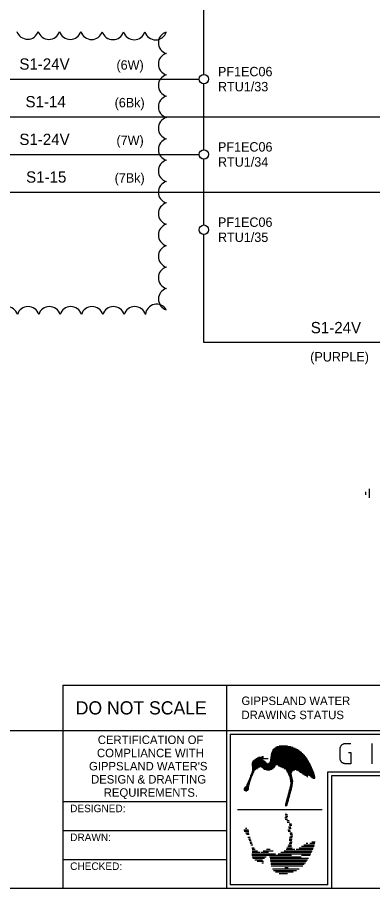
# Model space of a CAD drawing. Extents: x 0 to 841, y 0 to 594.
# Drawn here: x 580.4 to 674.9, y 15 to 246.4 of the extents above; entities that cross this region are included whole.
import ezdxf

# ---------------------------------------------------------------- set-up
doc = ezdxf.new("R2010")
doc.units = 0
for name, color, linetype in [('A1BORDER', 7, 'Continuous'), ('Level 1', 7, 'Continuous'), ('Level 10', 7, 'Continuous'), ('Level 2', 7, 'Continuous')]:
    doc.layers.add(name, color=color, linetype=linetype)

msp = doc.modelspace()

# ---------------------------------------------------------------- linework, layer by layer
at = {"layer": 'A1BORDER'}
for p, q in [((592.5, 69), (592.5, 15)), ((592.5, 69), (829, 69)), ((636, 69), (636, 15)), ((28, 57), (829, 57)), ((637, 56), (788, 56)), ((637, 56), (637, 16)), ((647.91, 50.92), (656.3, 50.92)), ((647.96, 51.12), (656.08, 51.12)), ((648.03, 51.32), (655.85, 51.32)), ((648.12, 51.52), (655.59, 51.52)), ((648.23, 51.72), (655.31, 51.72)), ((648.37, 51.92), (655, 51.92)), ((648.53, 52.12), (654.64, 52.12)), ((648.74, 52.32), (654.24, 52.32)), ((649.02, 52.52), (653.76, 52.52)), ((649.39, 52.72), (653.15, 52.72)), ((650.01, 52.92), (652.2, 52.92)), ((642.9, 48.72), (646.37, 48.72)), ((643.04, 48.92), (646.16, 48.92)), ((643.26, 49.12), (645.9, 49.12)), ((643.54, 49.32), (645.57, 49.32)), ((643.85, 49.52), (647.09, 49.52)), ((644.18, 49.72), (645.89, 49.72)), ((644.54, 49.92), (645.36, 49.92)), ((645.37, 50.12), (645.86, 50.12)), ((647.54, 48.72), (657.92, 48.72)), ((647.61, 48.92), (657.8, 48.92)), ((647.63, 49.12), (657.68, 49.12)), ((647.66, 49.32), (657.57, 49.32)), ((647.69, 49.52), (657.44, 49.52)), ((647.71, 49.72), (657.31, 49.72)), ((647.75, 49.92), (657.17, 49.92)), ((647.78, 50.12), (657.02, 50.12)), ((647.81, 50.32), (656.86, 50.32)), ((647.85, 50.52), (656.69, 50.52)), ((647.88, 50.72), (656.5, 50.72)), ((642.73, 48.12), (658.25, 48.12)), ((642.74, 47.92), (658.35, 47.92)), ((642.75, 48.32), (646.79, 48.32)), ((642.79, 47.72), (649.08, 47.72)), ((642.81, 48.52), (646.55, 48.52)), ((642.83, 47.52), (648.95, 47.52)), ((642.84, 46.32), (643.5, 46.32)), ((642.85, 47.31), (644.88, 47.31)), ((642.87, 47.12), (644.57, 47.12)), ((642.87, 46.52), (643.6, 46.52)), ((642.88, 46.92), (644.23, 46.92)), ((642.88, 46.72), (643.83, 46.72)), ((645.14, 47.31), (648.83, 47.31)), ((645.49, 47.12), (648.67, 47.12)), ((645.76, 46.92), (648.42, 46.92)), ((646.05, 46.72), (648.11, 46.72)), ((646.62, 46.52), (647.67, 46.52)), ((647.19, 48.32), (658.14, 48.32)), ((647.42, 48.52), (658.03, 48.52)), ((649.72, 47.72), (658.45, 47.72)), ((650.12, 47.52), (658.55, 47.52)), ((650.48, 47.31), (658.64, 47.31)), ((650.87, 47.12), (658.73, 47.12)), ((651.36, 46.92), (658.82, 46.92)), ((651.76, 46.72), (658.9, 46.72)), ((651.88, 46.52), (654.15, 46.52)), ((651.99, 46.32), (653.71, 46.32)), ((654.57, 46.52), (658.99, 46.52)), ((655, 46.32), (659.07, 46.32)), ((642.06, 44.12), (642.55, 44.12)), ((642.13, 44.32), (642.62, 44.32)), ((642.21, 44.52), (642.69, 44.52)), ((642.28, 44.72), (642.76, 44.72)), ((642.35, 44.92), (642.83, 44.92)), ((642.43, 45.12), (642.9, 45.12)), ((642.5, 45.32), (643, 45.32)), ((642.57, 45.52), (643.1, 45.52)), ((642.65, 45.72), (643.2, 45.72)), ((642.72, 45.92), (643.3, 45.92)), ((642.79, 46.12), (643.4, 46.12)), ((652.1, 46.12), (653.52, 46.12)), ((652.2, 45.92), (653.4, 45.92)), ((652.31, 45.72), (653.33, 45.72)), ((652.41, 45.52), (653.31, 45.52)), ((652.5, 45.32), (653.34, 45.32)), ((652.6, 45.12), (653.38, 45.12)), ((652.69, 44.92), (653.41, 44.92)), ((652.78, 44.72), (653.44, 44.72)), ((652.83, 44.52), (653.48, 44.52)), ((652.86, 44.32), (653.53, 44.32)), ((652.89, 44.12), (653.57, 44.12)), ((655.31, 46.12), (659.14, 46.12)), ((655.62, 45.92), (659.22, 45.92)), ((655.93, 45.72), (659.29, 45.72)), ((656.24, 45.52), (659.35, 45.52)), ((656.55, 45.32), (659.42, 45.32)), ((656.86, 45.12), (657.74, 45.12)), ((657.17, 44.92), (657.68, 44.92)), ((657.51, 44.72), (657.54, 44.72)), ((657.91, 45.12), (659.48, 45.12)), ((658.19, 44.92), (659.54, 44.92)), ((658.47, 44.72), (659.59, 44.72)), ((658.75, 44.52), (659.58, 44.52)), ((659.02, 44.32), (659.47, 44.32)), ((663, 46), (788, 46)), ((663, 16), (663, 46)), ((664, 45), (829, 45)), ((664, 15), (664, 45)), ((640.73, 41.72), (641.95, 41.72)), ((640.9, 41.92), (641.97, 41.92)), ((641.1, 42.12), (642, 42.12)), ((641.25, 42.31), (642.04, 42.31)), ((641.37, 42.52), (642.09, 42.52)), ((641.46, 42.72), (642.15, 42.72)), ((641.55, 42.92), (642.2, 42.92)), ((641.64, 43.12), (642.25, 43.12)), ((641.73, 43.32), (642.3, 43.32)), ((641.82, 43.51), (642.35, 43.51)), ((641.91, 43.72), (642.41, 43.72)), ((641.99, 43.92), (642.48, 43.92)), ((652.79, 41.72), (653.41, 41.72)), ((652.85, 41.92), (653.45, 41.92)), ((652.9, 42.12), (653.49, 42.12)), ((652.91, 43.92), (653.62, 43.92)), ((652.94, 43.72), (653.67, 43.72)), ((652.95, 42.31), (653.53, 42.31)), ((652.97, 43.51), (653.71, 43.51)), ((652.99, 42.52), (653.57, 42.52)), ((653, 43.32), (653.69, 43.32)), ((653.02, 43.12), (653.67, 43.12)), ((653.03, 42.72), (653.61, 42.72)), ((653.05, 42.92), (653.64, 42.92)), ((640.62, 41.32), (641.88, 41.32)), ((640.63, 41.52), (641.93, 41.52)), ((640.72, 41.12), (641.73, 41.12)), ((641.03, 40.92), (641.43, 40.92)), ((652.2, 39.52), (652.82, 39.52)), ((652.25, 39.72), (652.88, 39.72)), ((652.3, 39.92), (652.93, 39.92)), ((652.36, 40.12), (652.99, 40.12)), ((652.41, 40.32), (653.04, 40.32)), ((652.47, 40.52), (653.1, 40.52)), ((652.52, 40.72), (653.15, 40.72)), ((652.57, 40.92), (653.2, 40.92)), ((652.63, 41.12), (653.26, 41.12)), ((652.68, 41.32), (653.31, 41.32)), ((652.74, 41.52), (653.37, 41.52)), ((636, 38), (592.5, 38)), ((651.63, 37.32), (652.23, 37.32)), ((651.64, 37.12), (652.17, 37.12)), ((651.65, 37.52), (652.28, 37.52)), ((651.71, 37.72), (652.34, 37.72)), ((651.76, 37.92), (652.39, 37.92)), ((651.82, 38.12), (652.44, 38.12)), ((651.87, 38.32), (652.5, 38.32)), ((651.92, 38.52), (652.55, 38.52)), ((651.98, 38.72), (652.61, 38.72)), ((652.03, 38.92), (652.66, 38.92)), ((652.09, 39.12), (652.72, 39.12)), ((652.14, 39.32), (652.77, 39.32)), ((638.93, 35.98), (661.47, 35.98)), ((651.79, 36.92), (651.9, 36.92)), ((651.79, 35.04), (651.9, 35.04)), ((651.54, 33.84), (652.17, 33.84)), ((651.63, 34.64), (652.23, 34.64)), ((651.65, 33.44), (652.28, 33.44)), ((651.71, 34.24), (652.34, 34.24)), ((652.03, 33.04), (652.66, 33.04)), ((652.14, 32.64), (652.77, 32.64)), ((636, 30.34), (592.5, 30.34)), ((640.62, 30.64), (641.88, 30.64)), ((640.73, 30.24), (641.95, 30.24)), ((641.03, 31.04), (641.43, 31.04)), ((652.34, 30.64), (652.97, 30.64)), ((652.45, 30.24), (653.07, 30.24)), ((652.47, 31.44), (653.1, 31.44)), ((652.57, 31.04), (653.2, 31.04)), ((652.66, 32.24), (653.29, 32.24)), ((652.77, 31.84), (653.4, 31.84)), ((641.1, 29.84), (642, 29.84)), ((641.37, 29.44), (642.09, 29.44)), ((641.73, 28.64), (642.3, 28.64)), ((641.91, 28.24), (642.41, 28.24)), ((642.06, 27.84), (642.55, 27.84)), ((652.66, 27.84), (653.35, 27.84)), ((652.72, 28.24), (653.44, 28.24)), ((652.77, 28.64), (653.46, 28.64)), ((652.9, 29.84), (653.49, 29.84)), ((652.99, 29.44), (653.57, 29.44)), ((653.05, 29.04), (653.64, 29.04)), ((642.21, 27.44), (642.69, 27.44)), ((642.35, 27.04), (642.83, 27.04)), ((642.5, 26.64), (643, 26.64)), ((642.79, 25.84), (643.4, 25.84)), ((652.1, 25.84), (653.52, 25.84)), ((652.31, 26.24), (653.33, 26.24)), ((652.5, 26.64), (653.34, 26.64)), ((652.69, 27.04), (653.41, 27.04)), ((652.83, 27.44), (653.48, 27.44)), ((655.31, 25.84), (659.14, 25.84)), ((655.93, 26.24), (659.29, 26.24)), ((656.55, 26.64), (659.42, 26.64)), ((657.17, 27.04), (657.68, 27.04)), ((658.19, 27.04), (659.54, 27.04)), ((658.75, 27.44), (659.58, 27.44)), ((642.73, 23.84), (653.27, 23.84)), ((642.79, 24.24), (649.08, 24.24)), ((642.81, 23.44), (646.55, 23.44)), ((642.85, 24.65), (644.88, 24.65)), ((642.87, 25.44), (643.6, 25.44)), ((642.88, 25.04), (644.23, 25.04)), ((645.14, 24.65), (647.18, 24.65)), ((645.76, 25.04), (648.42, 25.04)), ((646.62, 25.44), (647.67, 25.44)), ((647.42, 23.44), (655.89, 23.44)), ((649.72, 24.24), (658.45, 24.24)), ((650.48, 24.65), (658.64, 24.65)), ((651.36, 25.04), (658.82, 25.04)), ((651.88, 25.44), (654.15, 25.44)), ((654.57, 25.44), (658.99, 25.44)), ((655.94, 23.84), (658.25, 23.84)), ((636, 22.67), (592.5, 22.67)), ((643.04, 23.04), (646.16, 23.04)), ((643.54, 22.64), (645.57, 22.64)), ((644.18, 22.24), (645.89, 22.24)), ((645.37, 21.84), (645.86, 21.84)), ((647.61, 23.04), (657.8, 23.04)), ((647.66, 22.64), (657.57, 22.64)), ((647.71, 22.24), (657.31, 22.24)), ((647.78, 21.84), (657.02, 21.84)), ((647.85, 21.44), (656.69, 21.44)), ((647.91, 21.04), (656.3, 21.04)), ((648.23, 20.24), (655.31, 20.24)), ((648.53, 19.84), (654.64, 19.84)), ((649.02, 19.44), (653.76, 19.44)), ((650.01, 19.04), (652.2, 19.04)), ((651.57, 20.64), (652.44, 20.64)), ((829, 15), (28, 15)), ((663, 16), (637, 16))]:
    msp.add_line(p, q, dxfattribs=at)
for points in [[(668.49, 51.15), (669.06, 51.15), (669.06, 48.16), (667.64, 48.16), (667.51, 48.16), (667.39, 48.18), (667.28, 48.21), (667.15, 48.25), (667.04, 48.3), (666.93, 48.36), (666.82, 48.43), (666.73, 48.51), (666.64, 48.6), (666.55, 48.7), (666.48, 48.8), (666.41, 48.91), (666.35, 49.02), (666.31, 49.14), (666.27, 49.27), (666.24, 49.39), (666.22, 49.52), (666.22, 49.66), (666.22, 52.05), (666.22, 52.18), (666.24, 52.31), (666.27, 52.43), (666.31, 52.56), (666.35, 52.67), (666.41, 52.79), (666.48, 52.9), (666.55, 53), (666.64, 53.1), (666.73, 53.19), (666.82, 53.27), (666.93, 53.34), (667.04, 53.4), (667.15, 53.45), (667.28, 53.49), (667.39, 53.52), (667.51, 53.54), (667.64, 53.54), (669.06, 53.54)], [(674.74, 48.16), (674.74, 53.54)]]:
    msp.add_lwpolyline(points, dxfattribs=at)
at = {"layer": 'Level 1'}
for p, q in [((630, 231.25), (630, 248.75)), ((280, 230), (628.75, 230)), ((630, 211.25), (630, 228.75)), ((280, 220), (685, 220)), ((280, 210), (628.75, 210)), ((630, 191.25), (630, 208.75)), ((280, 200), (685, 200)), ((630, 160), (630, 188.75)), ((685, 160), (630, 160))]:
    msp.add_line(p, q, dxfattribs=at)
for centre, radius, start, end in [((583.12, 243.57), 2.98, 197.2245, 342.2245), ((588.79, 243.54), 2.98, 197.2245, 342.2245), ((594.47, 243.52), 2.98, 197.2245, 342.2245), ((600.14, 243.49), 2.98, 197.2245, 342.2245), ((605.82, 243.46), 2.98, 197.2245, 342.2245), ((611.49, 243.44), 2.98, 197.2245, 342.2245), ((617.17, 243.41), 2.98, 197.2245, 342.2245), ((620.89, 239.66), 2.98, 107.5, 252.5), ((620.89, 233.99), 2.98, 107.5, 252.5), ((620.89, 228.31), 2.98, 107.5, 252.5), ((620.89, 222.64), 2.98, 107.5, 252.5), ((620.89, 216.96), 2.98, 107.5, 252.5), ((620.89, 211.29), 2.98, 107.5, 252.5), ((620.89, 205.61), 2.98, 107.5, 252.5), ((620.89, 199.94), 2.98, 107.5, 252.5), ((620.89, 194.27), 2.98, 107.5, 252.5), ((620.89, 188.59), 2.98, 107.5, 252.5), ((620.89, 182.92), 2.98, 107.5, 252.5), ((620.89, 177.24), 2.98, 107.5, 252.5), ((620.89, 171.57), 2.97, 107.5, 252.5), ((577.57, 166.61), 2.98, 17.5, 162.5), ((583.25, 166.61), 2.98, 17.5, 162.5), ((588.92, 166.61), 2.98, 17.5, 162.5), ((594.6, 166.61), 2.98, 17.5, 162.5), ((600.27, 166.61), 2.98, 17.5, 162.5), ((605.95, 166.61), 2.98, 17.5, 162.5), ((611.62, 166.61), 2.98, 17.5, 162.5), ((617.42, 167.24), 2.98, 30.0142, 175.0142)]:
    msp.add_arc(centre, radius, start, end, dxfattribs=at)
at = {"layer": 'Level 10'}
for p, q in [((673, 120.4), (673, 119.6)), ((674, 121.2), (674, 118.8))]:
    msp.add_line(p, q, dxfattribs=at)
for centre in [(630, 230), (630, 210), (630, 190)]:
    msp.add_circle(centre, 1.25, dxfattribs=at)

# ---------------------------------------------------------------- texts
at = {"layer": 'A1BORDER'}
for s, height, p in [('DO NOT SCALE', 3.5, (595.92, 61.25)), ('GIPPSLAND WATER', 2.25, (640, 63.75)), ('DRAWING STATUS', 2.25, (640, 60)), ('CERTIFICATION OF', 2.25, (601.79, 53.39)), ('COMPLIANCE WITH', 2.25, (601.57, 49.89)), ("GIPPSLAND WATER'S", 2.25, (599.45, 46.39)), ('DESIGN & DRAFTING', 2.25, (600, 42.89)), ('REQUIREMENTS.', 2.25, (603.37, 39.39)), ('DESIGNED:', 2, (594.44, 35.29)), ('DRAWN:', 2, (594.44, 27.62)), ('CHECKED:', 2, (594.44, 19.95))]:
    msp.add_text(s, height=height, dxfattribs=at).set_placement(p)
at = {"layer": 'Level 1'}
for s, height, p in [('S1-24V', 3, (580.93, 232.5)), ('(6W)', 2.5, (606.76, 232.5)), ('S1-14', 3, (582.57, 222.5)), ('(6Bk)', 2.5, (606.27, 222.5)), ('S1-24V', 3, (580.93, 212.5)), ('(7W)', 2.5, (606.76, 212.5)), ('S1-15', 3, (582.72, 202.5)), ('(7Bk)', 2.5, (606.27, 202.5)), ('S1-24V', 3, (658.43, 162.5)), ('(PURPLE)', 2.5, (658.28, 155))]:
    msp.add_text(s, height=height, dxfattribs=at).set_placement(p)
at = {"layer": 'Level 2'}
for s, p in [('PF1EC06', (633.75, 230.75)), ('RTU1/33', (633.75, 226.75)), ('PF1EC06', (633.75, 210.75)), ('RTU1/34', (633.75, 206.75)), ('PF1EC06', (633.75, 190.75)), ('RTU1/35', (633.75, 186.75))]:
    msp.add_text(s, height=2.5, dxfattribs=at).set_placement(p)

doc.saveas('drawing.dxf')
